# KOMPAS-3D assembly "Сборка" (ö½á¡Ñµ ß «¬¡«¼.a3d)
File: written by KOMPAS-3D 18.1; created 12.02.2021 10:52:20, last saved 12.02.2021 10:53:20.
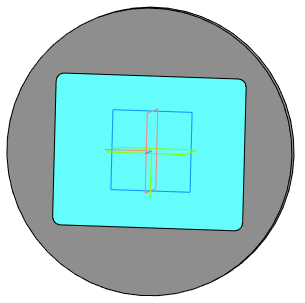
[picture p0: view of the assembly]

Document properties: Полное имя файла: C:\GoogleDrive\НИР\ИКИ\Компас\Фланец с окном.a3d

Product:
- Part/product: Сборка
    Масса: 1.46022
  - Component [detail]: Деталь  | Масса: 1.10521; source file: Фланец без окна.m3d
  - Component [detail]: Деталь  | Материал: Стекло БК10  ГОСТ 3514-94 (density 3120 kg/m3); Масса: 0.35501; source file: Окно фланца.m3d

Referenced files in C:\GoogleDrive\НИР\ИКИ\Компас\: Фланец без окна.m3d, Окно фланца.m3d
